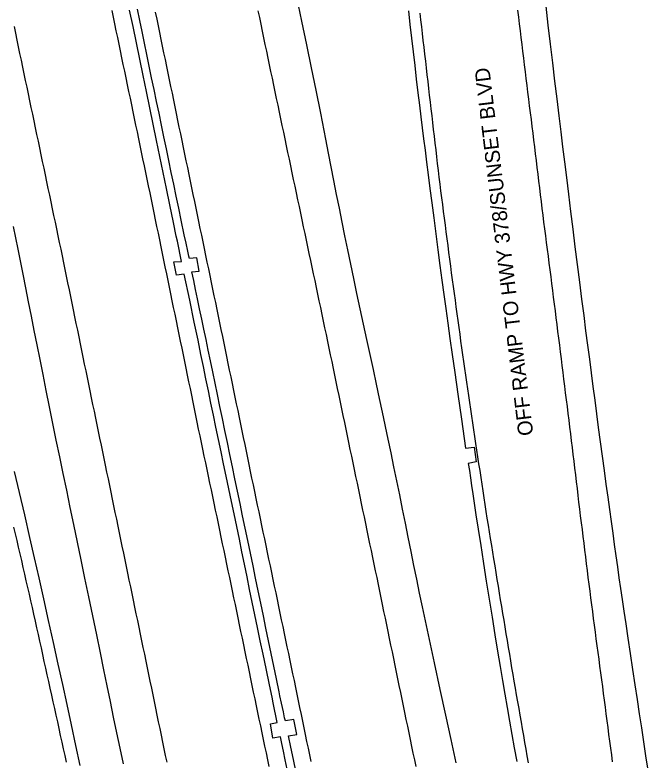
# Model space of a CAD drawing. Extents: x 1948091 to 1975253, y 787267 to 823306.
# Drawn here: x 1966599.2 to 1966828.7, y 789115.5 to 789385.7 of the extents above; entities that cross this region are included whole.
import ezdxf

# ---------------------------------------------------------------- set-up
doc = ezdxf.new("R2010")
doc.units = 0
for name, color, linetype in [('RD_EX_Pavement_Markings', 7, 'Continuous'), ('RD_EX_Road', 7, 'Continuous'), ('RD_TX_RoadID', 7, 'Continuous')]:
    doc.layers.add(name, color=color, linetype=linetype)

msp = doc.modelspace()

# ---------------------------------------------------------------- linework, layer by layer
at = {"layer": 'RD_EX_Pavement_Markings'}
for points in [[(1966634.28, 789387.33), (1966634.79, 789384.88), (1966635.3, 789382.44), (1966635.81, 789379.99), (1966636.32, 789377.54), (1966636.83, 789375.1), (1966637.34, 789372.65), (1966637.85, 789370.2), (1966638.36, 789367.75), (1966638.87, 789365.31), (1966639.38, 789362.86), (1966639.89, 789360.41), (1966640.4, 789357.96), (1966640.91, 789355.52), (1966641.42, 789353.07), (1966641.93, 789350.62), (1966642.44, 789348.17), (1966642.95, 789345.73), (1966643.45, 789343.28), (1966643.96, 789340.83), (1966644.47, 789338.38), (1966644.98, 789335.94), (1966645.49, 789333.49), (1966646, 789331.04), (1966646.51, 789328.59), (1966647.02, 789326.15), (1966647.53, 789323.7), (1966648.04, 789321.25), (1966648.54, 789318.8), (1966649.05, 789316.35), (1966649.55, 789313.91), (1966650.06, 789311.46), (1966650.56, 789309.01), (1966651.06, 789306.56), (1966651.57, 789304.11), (1966652.07, 789301.66), (1966652.57, 789299.21), (1966653.08, 789296.76), (1966653.58, 789294.32), (1966654.09, 789291.87), (1966654.59, 789289.42), (1966655.09, 789286.97), (1966655.6, 789284.52), (1966656.1, 789282.07), (1966656.6, 789279.62), (1966657.11, 789277.17), (1966657.61, 789274.73), (1966658.12, 789272.28), (1966658.62, 789269.83), (1966659.12, 789267.38), (1966659.63, 789264.93), (1966660.13, 789262.48), (1966660.64, 789260.03), (1966661.14, 789257.59), (1966661.64, 789255.14), (1966662.15, 789252.69), (1966662.65, 789250.24), (1966663.15, 789247.79), (1966663.66, 789245.34), (1966664.16, 789242.89), (1966664.67, 789240.44), (1966665.17, 789238), (1966665.67, 789235.55), (1966666.18, 789233.1), (1966666.69, 789230.65), (1966667.21, 789228.21), (1966667.72, 789225.76), (1966668.23, 789223.31), (1966668.74, 789220.86), (1966669.25, 789218.42), (1966669.76, 789215.97), (1966670.27, 789213.52), (1966670.78, 789211.08), (1966671.29, 789208.63), (1966671.81, 789206.18), (1966672.32, 789203.73), (1966672.83, 789201.29), (1966673.34, 789198.84), (1966673.85, 789196.39), (1966674.36, 789193.95), (1966674.87, 789191.5), (1966675.38, 789189.05), (1966675.89, 789186.6), (1966676.4, 789184.16), (1966676.92, 789181.71), (1966677.43, 789179.26), (1966677.94, 789176.82), (1966678.45, 789174.37), (1966678.96, 789171.92), (1966679.47, 789169.47), (1966679.98, 789167.03), (1966680.49, 789164.58), (1966681, 789162.13), (1966681.52, 789159.69), (1966682.03, 789157.24), (1966682.54, 789154.79), (1966683.05, 789152.34), (1966683.56, 789149.9), (1966684.07, 789147.45), (1966684.58, 789145), (1966685.09, 789142.55), (1966685.6, 789140.11), (1966686.11, 789137.66), (1966686.62, 789135.21), (1966687.13, 789132.77), (1966687.65, 789130.32), (1966688.16, 789127.87), (1966688.67, 789125.42), (1966689.18, 789122.98), (1966689.69, 789120.53), (1966690.2, 789118.08), (1966690.71, 789115.64), (1966691.22, 789113.19)], [(1966687.27, 789387.21), (1966687.78, 789384.77), (1966688.29, 789382.32), (1966688.8, 789379.87), (1966689.31, 789377.43), (1966689.82, 789374.98), (1966690.33, 789372.53), (1966690.85, 789370.08), (1966691.36, 789367.64), (1966691.87, 789365.19), (1966692.38, 789362.74), (1966692.89, 789360.3), (1966693.4, 789357.85), (1966693.91, 789355.4), (1966694.43, 789352.95), (1966694.94, 789350.51), (1966695.46, 789348.06), (1966695.97, 789345.62), (1966696.49, 789343.17), (1966697, 789340.72), (1966697.52, 789338.28), (1966698.04, 789335.83), (1966698.55, 789333.39), (1966699.07, 789330.94), (1966699.58, 789328.49), (1966700.1, 789326.05), (1966700.62, 789323.6), (1966701.13, 789321.15), (1966701.65, 789318.71), (1966702.16, 789316.26), (1966702.68, 789313.82), (1966703.2, 789311.37), (1966703.71, 789308.92), (1966704.23, 789306.48), (1966704.74, 789304.03), (1966705.26, 789301.59), (1966705.78, 789299.14), (1966706.29, 789296.69), (1966706.81, 789294.25), (1966707.32, 789291.8), (1966707.84, 789289.35), (1966708.35, 789286.91), (1966708.87, 789284.46), (1966709.39, 789282.02), (1966709.9, 789279.57), (1966710.42, 789277.12), (1966710.93, 789274.68), (1966711.45, 789272.23), (1966711.96, 789269.79), (1966712.47, 789267.34), (1966712.98, 789264.89), (1966713.49, 789262.44), (1966714, 789260), (1966714.51, 789257.55), (1966715.02, 789255.1), (1966715.53, 789252.65), (1966716.04, 789250.21), (1966716.55, 789247.76), (1966717.06, 789245.31), (1966717.57, 789242.86), (1966718.08, 789240.42), (1966718.59, 789237.97), (1966719.1, 789235.52), (1966719.61, 789233.07), (1966720.12, 789230.63), (1966720.63, 789228.18), (1966721.14, 789225.73), (1966721.65, 789223.28), (1966722.16, 789220.84), (1966722.67, 789218.39), (1966723.18, 789215.94), (1966723.69, 789213.49), (1966724.2, 789211.05), (1966724.71, 789208.6), (1966725.22, 789206.15), (1966725.73, 789203.71), (1966726.24, 789201.26), (1966726.75, 789198.81), (1966727.26, 789196.36), (1966727.77, 789193.92), (1966728.28, 789191.47), (1966728.79, 789189.02), (1966729.3, 789186.57), (1966729.81, 789184.13), (1966730.31, 789181.68), (1966730.82, 789179.23), (1966731.33, 789176.78), (1966731.83, 789174.33), (1966732.34, 789171.88), (1966732.84, 789169.44), (1966733.35, 789166.99), (1966733.85, 789164.54), (1966734.36, 789162.09), (1966734.86, 789159.64), (1966735.37, 789157.19), (1966735.88, 789154.75), (1966736.38, 789152.3), (1966736.89, 789149.85), (1966737.39, 789147.4), (1966737.9, 789144.95), (1966738.4, 789142.5), (1966738.91, 789140.06), (1966739.41, 789137.61), (1966739.92, 789135.16), (1966740.43, 789132.71), (1966740.93, 789130.26), (1966741.44, 789127.81), (1966741.94, 789125.37), (1966742.45, 789122.92), (1966742.95, 789120.47), (1966743.46, 789118.02), (1966743.96, 789115.57), (1966744.47, 789113.12)], [(1966815.82, 789114.9), (1966815.49, 789117.37), (1966815.16, 789119.85), (1966814.84, 789122.33), (1966814.51, 789124.8), (1966814.19, 789127.28), (1966813.86, 789129.75), (1966813.53, 789132.23), (1966813.21, 789134.71), (1966812.88, 789137.18), (1966812.55, 789139.66), (1966812.23, 789142.13), (1966811.9, 789144.61), (1966811.57, 789147.09), (1966811.24, 789149.56), (1966810.91, 789152.04), (1966810.58, 789154.51), (1966810.25, 789156.99), (1966809.92, 789159.46), (1966809.59, 789161.94), (1966809.26, 789164.41), (1966808.93, 789166.89), (1966808.6, 789169.36), (1966808.26, 789171.84), (1966807.95, 789174.31), (1966807.64, 789176.79), (1966807.33, 789179.27), (1966807.02, 789181.74), (1966806.71, 789184.22), (1966806.4, 789186.7), (1966806.09, 789189.18), (1966805.78, 789191.65), (1966805.47, 789194.13), (1966805.17, 789196.61), (1966804.86, 789199.09), (1966804.55, 789201.56), (1966804.24, 789204.04), (1966803.94, 789206.52), (1966803.64, 789209), (1966803.34, 789211.48), (1966803.04, 789213.96), (1966802.74, 789216.44), (1966802.44, 789218.92), (1966802.14, 789221.39), (1966801.84, 789223.87), (1966801.54, 789226.35), (1966801.24, 789228.83), (1966800.94, 789231.31), (1966800.65, 789233.79), (1966800.35, 789236.27), (1966800.04, 789238.74), (1966799.73, 789241.22), (1966799.43, 789243.7), (1966799.12, 789246.18), (1966798.81, 789248.65), (1966798.5, 789251.13), (1966798.19, 789253.61), (1966797.88, 789256.09), (1966797.57, 789258.56), (1966797.26, 789261.04), (1966796.96, 789263.52), (1966796.65, 789265.99), (1966796.34, 789268.47), (1966796.03, 789270.95), (1966795.72, 789273.43), (1966795.41, 789275.91), (1966795.09, 789278.38), (1966794.77, 789280.86), (1966794.45, 789283.33), (1966794.13, 789285.81), (1966793.82, 789288.29), (1966793.5, 789290.76), (1966793.18, 789293.24), (1966792.86, 789295.72), (1966792.54, 789298.19), (1966792.22, 789300.67), (1966791.9, 789303.15), (1966791.59, 789305.62), (1966791.27, 789308.1), (1966790.95, 789310.58), (1966790.63, 789313.05), (1966790.33, 789315.53), (1966790.02, 789318.01), (1966789.72, 789320.49), (1966789.41, 789322.97), (1966789.11, 789325.45), (1966788.8, 789327.93), (1966788.5, 789330.4), (1966788.19, 789332.88), (1966787.89, 789335.36), (1966787.58, 789337.84), (1966787.28, 789340.32), (1966786.98, 789342.8), (1966786.67, 789345.28), (1966786.37, 789347.75), (1966786.06, 789350.23), (1966785.76, 789352.71), (1966785.46, 789355.19), (1966785.15, 789357.67), (1966784.85, 789360.15), (1966784.54, 789362.62), (1966784.24, 789365.1), (1966783.94, 789367.58), (1966783.63, 789370.06), (1966783.33, 789372.54), (1966783.02, 789375.01), (1966782.72, 789377.49), (1966782.42, 789379.97), (1966782.11, 789382.45), (1966781.82, 789384.93), (1966781.52, 789387.41)], [(1966650.07, 789386.66), (1966650.58, 789384.21), (1966651.08, 789381.76), (1966651.59, 789379.31), (1966652.09, 789376.86), (1966652.6, 789374.42), (1966653.1, 789371.97), (1966653.61, 789369.52), (1966654.11, 789367.07), (1966654.62, 789364.62), (1966655.12, 789362.17), (1966655.63, 789359.73), (1966656.13, 789357.28), (1966656.64, 789354.83), (1966657.14, 789352.38), (1966657.65, 789349.93), (1966658.15, 789347.48), (1966658.66, 789345.03), (1966659.16, 789342.59), (1966659.67, 789340.14), (1966660.17, 789337.69), (1966660.68, 789335.24), (1966661.19, 789332.79), (1966661.69, 789330.35), (1966662.2, 789327.9), (1966662.71, 789325.45), (1966663.22, 789323), (1966663.72, 789320.55), (1966664.23, 789318.11), (1966664.74, 789315.66), (1966665.24, 789313.21), (1966665.75, 789310.76), (1966666.26, 789308.31), (1966666.77, 789305.87), (1966667.27, 789303.42), (1966667.78, 789300.97), (1966668.29, 789298.52), (1966668.79, 789296.07), (1966669.3, 789293.63), (1966669.81, 789291.18), (1966670.32, 789288.73), (1966670.82, 789286.28), (1966671.33, 789283.83), (1966671.84, 789281.39), (1966672.34, 789278.94), (1966672.85, 789276.49), (1966673.36, 789274.04), (1966673.86, 789271.59), (1966674.37, 789269.15), (1966674.88, 789266.7), (1966675.38, 789264.25), (1966675.89, 789261.8), (1966676.39, 789259.35), (1966676.9, 789256.9), (1966677.41, 789254.46), (1966677.91, 789252.01), (1966678.42, 789249.56), (1966678.93, 789247.11), (1966679.43, 789244.66), (1966679.94, 789242.22), (1966680.44, 789239.77), (1966680.95, 789237.32), (1966681.46, 789234.87), (1966681.96, 789232.42), (1966682.47, 789229.97), (1966682.98, 789227.53), (1966683.48, 789225.08), (1966683.99, 789222.63), (1966684.49, 789220.18), (1966685, 789217.73), (1966685.51, 789215.29), (1966686.02, 789212.84), (1966686.53, 789210.39), (1966687.04, 789207.94), (1966687.55, 789205.5), (1966688.06, 789203.05), (1966688.58, 789200.6), (1966689.09, 789198.16), (1966689.6, 789195.71), (1966690.11, 789193.26), (1966690.62, 789190.82), (1966691.14, 789188.37), (1966691.65, 789185.92), (1966692.16, 789183.47), (1966692.67, 789181.03), (1966693.18, 789178.58), (1966693.7, 789176.13), (1966694.21, 789173.69), (1966694.72, 789171.24), (1966695.23, 789168.79), (1966695.74, 789166.35), (1966696.26, 789163.9), (1966696.77, 789161.45), (1966697.28, 789159.01), (1966697.79, 789156.56), (1966698.3, 789154.11), (1966698.82, 789151.66), (1966699.33, 789149.22), (1966699.84, 789146.77), (1966700.35, 789144.32), (1966700.85, 789141.87), (1966701.36, 789139.43), (1966701.87, 789136.98), (1966702.38, 789134.53), (1966702.89, 789132.08), (1966703.4, 789129.64), (1966703.91, 789127.19), (1966704.42, 789124.74), (1966704.93, 789122.29), (1966705.44, 789119.85), (1966705.95, 789117.4), (1966706.46, 789114.95)], [(1966745.94, 789386.37), (1966746.23, 789383.89), (1966746.52, 789381.41), (1966746.8, 789378.93), (1966747.09, 789376.45), (1966747.38, 789373.97), (1966747.66, 789371.48), (1966747.95, 789369), (1966748.24, 789366.52), (1966748.52, 789364.04), (1966748.81, 789361.56), (1966749.1, 789359.08), (1966749.38, 789356.6), (1966749.67, 789354.12), (1966749.96, 789351.64), (1966750.25, 789349.16), (1966750.54, 789346.68), (1966750.83, 789344.2), (1966751.12, 789341.72), (1966751.41, 789339.24), (1966751.7, 789336.76), (1966751.99, 789334.28), (1966752.28, 789331.8), (1966752.57, 789329.32), (1966752.86, 789326.84), (1966753.17, 789324.36), (1966753.49, 789321.88), (1966753.81, 789319.41), (1966754.13, 789316.93), (1966754.45, 789314.45), (1966754.77, 789311.98), (1966755.09, 789309.5), (1966755.41, 789307.02), (1966755.73, 789304.55), (1966756.05, 789302.07), (1966756.37, 789299.6), (1966756.68, 789297.12), (1966757.01, 789294.64), (1966757.35, 789292.17), (1966757.69, 789289.7), (1966758.03, 789287.22), (1966758.37, 789284.75), (1966758.7, 789282.28), (1966759.04, 789279.8), (1966759.38, 789277.33), (1966759.72, 789274.85), (1966760.06, 789272.38), (1966760.4, 789269.91), (1966760.74, 789267.43), (1966761.08, 789264.96), (1966761.43, 789262.49), (1966761.79, 789260.02), (1966762.15, 789257.54), (1966762.51, 789255.07), (1966762.87, 789252.6), (1966763.23, 789250.13), (1966763.59, 789247.66), (1966763.94, 789245.18), (1966764.3, 789242.71), (1966764.66, 789240.24), (1966765.02, 789237.77), (1966765.38, 789235.3), (1966765.75, 789232.83), (1966766.13, 789230.36), (1966766.51, 789227.89), (1966766.88, 789225.42), (1966767.26, 789222.95), (1966767.64, 789220.48), (1966768.02, 789218.02), (1966768.39, 789215.55), (1966768.77, 789213.08), (1966769.15, 789210.61), (1966769.52, 789208.14), (1966769.9, 789205.67), (1966770.29, 789203.21), (1966770.69, 789200.74), (1966771.09, 789198.28), (1966771.49, 789195.81), (1966771.9, 789193.35), (1966772.3, 789190.88), (1966772.7, 789188.42), (1966773.1, 789185.95), (1966773.51, 789183.49), (1966773.91, 789181.02), (1966774.31, 789178.56), (1966774.72, 789176.09), (1966775.12, 789173.63), (1966775.53, 789171.16), (1966775.94, 789168.7), (1966776.35, 789166.24), (1966776.76, 789163.77), (1966777.17, 789161.31), (1966777.58, 789158.84), (1966777.99, 789156.38), (1966778.4, 789153.92), (1966778.81, 789151.45), (1966779.22, 789148.99), (1966779.63, 789146.52), (1966780.05, 789144.06), (1966780.48, 789141.6), (1966780.92, 789139.14), (1966781.35, 789136.68), (1966781.78, 789134.22), (1966782.21, 789131.76), (1966782.64, 789129.3), (1966783.07, 789126.84), (1966783.5, 789124.38), (1966783.93, 789121.92), (1966784.36, 789119.46), (1966784.79, 789117), (1966785.23, 789114.54)], [(1966598.88, 789381.51), (1966599.38, 789379.06), (1966599.89, 789376.61), (1966600.39, 789374.16), (1966600.9, 789371.72), (1966601.4, 789369.27), (1966601.91, 789366.82), (1966602.43, 789364.37), (1966602.94, 789361.93), (1966603.45, 789359.48), (1966603.97, 789357.04), (1966604.48, 789354.59), (1966605, 789352.14), (1966605.51, 789349.7), (1966606.02, 789347.25), (1966606.54, 789344.8), (1966607.05, 789342.36), (1966607.57, 789339.91), (1966608.08, 789337.46), (1966608.59, 789335.02), (1966609.11, 789332.57), (1966609.62, 789330.12), (1966610.13, 789327.68), (1966610.65, 789325.23), (1966611.16, 789322.78), (1966611.68, 789320.34), (1966612.19, 789317.89), (1966612.7, 789315.44), (1966613.22, 789313), (1966613.73, 789310.55), (1966614.25, 789308.1), (1966614.76, 789305.66), (1966615.27, 789303.21), (1966615.78, 789300.76), (1966616.28, 789298.31), (1966616.78, 789295.86), (1966617.29, 789293.42), (1966617.79, 789290.97), (1966618.3, 789288.52), (1966618.8, 789286.07), (1966619.3, 789283.62), (1966619.81, 789281.17), (1966620.31, 789278.72), (1966620.81, 789276.28), (1966621.32, 789273.83), (1966621.82, 789271.38), (1966622.33, 789268.93), (1966622.83, 789266.48), (1966623.33, 789264.03), (1966623.84, 789261.58), (1966624.34, 789259.13), (1966624.84, 789256.69), (1966625.35, 789254.24), (1966625.85, 789251.79), (1966626.36, 789249.34), (1966626.86, 789246.89), (1966627.36, 789244.44), (1966627.87, 789241.99), (1966628.37, 789239.54), (1966628.88, 789237.1), (1966629.38, 789234.65), (1966629.89, 789232.2), (1966630.4, 789229.75), (1966630.9, 789227.3), (1966631.41, 789224.86), (1966631.92, 789222.41), (1966632.42, 789219.96), (1966632.93, 789217.51), (1966633.44, 789215.06), (1966633.94, 789212.62), (1966634.45, 789210.17), (1966634.96, 789207.72), (1966635.46, 789205.27), (1966635.97, 789202.82), (1966636.48, 789200.38), (1966636.98, 789197.93), (1966637.49, 789195.48), (1966638, 789193.03), (1966638.51, 789190.58), (1966639.01, 789188.14), (1966639.52, 789185.69), (1966640.03, 789183.24), (1966640.53, 789180.79), (1966641.04, 789178.34), (1966641.55, 789175.9), (1966642.05, 789173.45), (1966642.56, 789171), (1966643.07, 789168.55), (1966643.57, 789166.1), (1966644.08, 789163.66), (1966644.59, 789161.21), (1966645.09, 789158.76), (1966645.6, 789156.31), (1966646.1, 789153.86), (1966646.61, 789151.41), (1966647.12, 789148.97), (1966647.62, 789146.52), (1966648.13, 789144.07), (1966648.64, 789141.62), (1966649.14, 789139.17), (1966649.65, 789136.73), (1966650.16, 789134.28), (1966650.66, 789131.83), (1966651.17, 789129.38), (1966651.68, 789126.93), (1966652.18, 789124.48), (1966652.69, 789122.04), (1966653.19, 789119.59), (1966653.7, 789117.14), (1966654.21, 789114.69)], [(1966598.7, 789199.98), (1966599.27, 789197.55), (1966599.84, 789195.12), (1966600.41, 789192.69), (1966600.97, 789190.26), (1966601.53, 789187.83), (1966602.08, 789185.39), (1966602.64, 789182.96), (1966603.2, 789180.53), (1966603.76, 789178.09), (1966604.31, 789175.66), (1966604.86, 789173.23), (1966605.41, 789170.79), (1966605.96, 789168.36), (1966606.51, 789165.92), (1966607.06, 789163.49), (1966607.6, 789161.05), (1966608.13, 789158.61), (1966608.67, 789156.17), (1966609.2, 789153.73), (1966609.73, 789151.29), (1966610.27, 789148.85), (1966610.8, 789146.41), (1966611.34, 789143.98), (1966611.88, 789141.54), (1966612.42, 789139.1), (1966612.96, 789136.66), (1966613.5, 789134.22), (1966614.03, 789131.78), (1966614.57, 789129.35), (1966615.11, 789126.91), (1966615.65, 789124.47), (1966616.19, 789122.03), (1966616.73, 789119.59), (1966617.27, 789117.15), (1966617.8, 789114.72)]]:
    msp.add_lwpolyline(points, dxfattribs=at)
at = {"layer": 'RD_EX_Road'}
for points in [[(1966759.13, 789114.48), (1966757.3, 789122.96), (1966755.39, 789131.74), (1966753.36, 789141.06), (1966751.24, 789150.82), (1966750.14, 789155.85), (1966749.04, 789160.93), (1966747.96, 789165.99), (1966746.9, 789171.03), (1966745.86, 789176.05), (1966744.83, 789181.07), (1966743.8, 789186.12), (1966742.77, 789191.18), (1966741.75, 789196.28), (1966740.73, 789201.39), (1966739.7, 789206.51), (1966738.66, 789211.64), (1966737.6, 789216.79), (1966736.55, 789221.9), (1966735.51, 789226.93), (1966734.48, 789231.88), (1966732.43, 789241.63), (1966731.35, 789246.66), (1966730.24, 789251.82), (1966729.1, 789257.12), (1966727.93, 789262.52), (1966726.74, 789267.99), (1966725.54, 789273.53), (1966724.33, 789279.13), (1966723.13, 789284.69), (1966721.99, 789290.11), (1966720.89, 789295.38), (1966719.84, 789300.51), (1966718.82, 789305.55), (1966717.8, 789310.59), (1966716.79, 789315.62), (1966715.79, 789320.63), (1966714.79, 789325.64), (1966713.81, 789330.64), (1966712.84, 789335.62), (1966711.87, 789340.6), (1966710.04, 789350.04), (1966708.35, 789358.46), (1966706.7, 789366.51), (1966705, 789374.83), (1966703.22, 789383.41), (1966701.38, 789392.25)], [(1966697.85, 789112.22), (1966697.15, 789115.63), (1966696.51, 789118.72), (1966695.93, 789121.49), (1966695.43, 789123.94), (1966692.73, 789123.48), (1966691.77, 789128.59), (1966694.3, 789129.19), (1966692.83, 789136.32), (1966692.42, 789138.32), (1966691.49, 789142.81), (1966690.26, 789148.67), (1966689.16, 789153.89), (1966688.13, 789158.76), (1966687.13, 789163.53), (1966686.16, 789168.22), (1966685.21, 789172.82), (1966684.27, 789177.38), (1966683.34, 789181.94), (1966682.41, 789186.49), (1966681.48, 789191.05), (1966680.54, 789195.6), (1966679.6, 789200.17), (1966678.65, 789204.74), (1966677.69, 789209.31), (1966676.73, 789213.88), (1966675.78, 789218.4), (1966674.83, 789222.89), (1966673.89, 789227.34), (1966672.96, 789231.76), (1966672.03, 789236.18), (1966671.12, 789240.59), (1966670.22, 789244.98), (1966669.33, 789249.38), (1966668.43, 789253.78), (1966667.52, 789258.19), (1966666.61, 789262.6), (1966665.55, 789267.73), (1966664.19, 789274.29), (1966662.53, 789282.28), (1966660.57, 789291.71), (1966657.78, 789291.33), (1966656.85, 789296.14), (1966659.55, 789296.35), (1966658.08, 789303.63), (1966657.69, 789305.5), (1966656.68, 789310.46), (1966655.37, 789316.86), (1966654.14, 789322.81), (1966652.95, 789328.57), (1966651.75, 789334.37), (1966650.53, 789340.21), (1966649.31, 789346.09), (1966648.08, 789351.99), (1966646.86, 789357.9), (1966645.65, 789363.79), (1966644.44, 789369.69), (1966643.23, 789375.59), (1966642.01, 789381.49), (1966640.77, 789387.4)], [(1966701.12, 789111), (1966700.13, 789115.76), (1966699.2, 789120.18), (1966698.33, 789124.28), (1966701.36, 789124.82), (1966700.32, 789130.19), (1966697.23, 789129.7), (1966696.96, 789130.84), (1966696.49, 789132.99), (1966695.82, 789136.15), (1966695.27, 789138.83), (1966694.95, 789140.31), (1966693.99, 789144.97), (1966693.03, 789149.6), (1966692.08, 789154.19), (1966691.13, 789158.75), (1966690.19, 789163.29), (1966689.25, 789167.83), (1966688.32, 789172.36), (1966687.38, 789176.9), (1966686.44, 789181.44), (1966685.5, 789185.98), (1966684.56, 789190.53), (1966683.61, 789195.08), (1966682.67, 789199.62), (1966681.73, 789204.12), (1966680.79, 789208.59), (1966679.86, 789213.03), (1966678.93, 789217.45), (1966678.01, 789221.86), (1966677.1, 789226.27), (1966676.2, 789230.67), (1966675.3, 789235.06), (1966674.4, 789239.41), (1966673.51, 789243.72), (1966672.63, 789248.01), (1966671.75, 789252.22), (1966670.9, 789256.32), (1966670.07, 789260.3), (1966669.26, 789264.17), (1966668.47, 789267.97), (1966667.69, 789271.72), (1966666.91, 789275.44), (1966666.14, 789279.13), (1966665.4, 789282.71), (1966664.69, 789286.14), (1966664.01, 789289.41), (1966663.37, 789292.53), (1966666.02, 789292.83), (1966665.16, 789297.6), (1966662.42, 789297.35), (1966662.23, 789298.18), (1966661.83, 789300.05), (1966661.22, 789302.94), (1966660.58, 789306.02), (1966659.49, 789311.28), (1966658.57, 789315.66), (1966657.67, 789320.01), (1966656.77, 789324.32), (1966655.88, 789328.61), (1966654.99, 789332.91), (1966654.1, 789337.2), (1966653.21, 789341.49), (1966652.32, 789345.78), (1966651.43, 789350.07), (1966650.54, 789354.37), (1966649.64, 789358.66), (1966648.75, 789362.94), (1966647.87, 789367.18), (1966647, 789371.38), (1966646.15, 789375.53), (1966645.31, 789379.65), (1966644.47, 789383.74), (1966643.63, 789387.79)], [(1966741.79, 789387.14), (1966742.36, 789382.23), (1966742.94, 789377.27), (1966743.52, 789372.3), (1966744.1, 789367.33), (1966744.68, 789362.36), (1966745.25, 789357.52), (1966745.8, 789352.98), (1966746.32, 789348.73), (1966746.82, 789344.77), (1966747.32, 789340.84), (1966747.85, 789336.69), (1966748.4, 789332.3), (1966748.99, 789327.69), (1966749.6, 789322.8), (1966750.26, 789317.61), (1966750.97, 789312.12), (1966751.71, 789306.32), (1966752.47, 789300.48), (1966753.21, 789294.88), (1966753.93, 789289.51), (1966754.63, 789284.39), (1966755.34, 789279.27), (1966756.08, 789273.94), (1966756.85, 789268.38), (1966757.66, 789262.61), (1966758.58, 789256.08), (1966759.71, 789248.24), (1966761.03, 789239.1), (1966762.56, 789228.66), (1966765.59, 789229.02), (1966766.35, 789223.6), (1966763.53, 789223.07), (1966763.9, 789220.52), (1966764.3, 789217.84), (1966764.71, 789215.04), (1966765.14, 789212.11), (1966765.65, 789208.69), (1966766.3, 789204.41), (1966767.09, 789199.27), (1966768.01, 789193.28), (1966768.39, 789190.87), (1966769.02, 789186.84), (1966770.04, 789180.36), (1966771.09, 789173.86), (1966772.14, 789167.33), (1966773.18, 789160.98), (1966774.16, 789155.03), (1966775.09, 789149.49), (1966775.95, 789144.35), (1966776.79, 789139.42), (1966777.64, 789134.52), (1966778.48, 789129.65), (1966779.33, 789124.8), (1966780.2, 789119.93), (1966781.08, 789114.99)], [(1966828.68, 789111.9), (1966827.9, 789117.02), (1966827.12, 789122.13), (1966826.36, 789127.22), (1966825.61, 789132.3), (1966824.84, 789137.48), (1966824.05, 789142.84), (1966823.21, 789148.4), (1966822.35, 789154.15), (1966821.5, 789159.76), (1966820.73, 789164.89), (1966820.03, 789169.54), (1966819.41, 789173.72), (1966818.83, 789177.67), (1966818.25, 789181.64), (1966817.68, 789185.62), (1966817.12, 789189.62), (1966816.55, 789193.67), (1966815.97, 789197.81), (1966815.38, 789202.03), (1966814.78, 789206.34), (1966814.16, 789210.82), (1966813.51, 789215.53), (1966812.84, 789220.48), (1966812.13, 789225.67), (1966811.43, 789230.92), (1966810.74, 789236.06), (1966810.08, 789241.1), (1966809.45, 789246.02), (1966808.82, 789250.92), (1966808.18, 789255.87), (1966807.53, 789260.88), (1966806.87, 789265.94), (1966806.18, 789271.19), (1966805.46, 789276.76), (1966804.7, 789282.65), (1966803.9, 789288.86), (1966803.08, 789295.24), (1966802.27, 789301.62), (1966801.48, 789308.02), (1966800.69, 789314.44), (1966799.93, 789320.71), (1966799.19, 789326.71), (1966798.49, 789332.44), (1966797.83, 789337.88), (1966797.16, 789343.34), (1966796.45, 789349.12), (1966795.71, 789355.23), (1966794.94, 789361.66), (1966794.14, 789368.3), (1966793.34, 789375.06), (1966792.52, 789381.94), (1966791.7, 789388.94)], [(1966598.54, 789308.99), (1966600.25, 789300.76), (1966602.05, 789291.72), (1966603.02, 789286.75), (1966604.01, 789281.62), (1966605.03, 789276.47), (1966606.06, 789271.3), (1966607.11, 789266.1), (1966608.18, 789260.79), (1966609.29, 789255.27), (1966610.44, 789249.55), (1966611.62, 789243.63), (1966612.82, 789237.61), (1966614.05, 789231.56), (1966615.29, 789225.51), (1966616.55, 789219.44), (1966617.83, 789213.33), (1966619.11, 789207.14), (1966620.4, 789200.88), (1966621.71, 789194.55), (1966623.03, 789188.09), (1966624.41, 789181.48), (1966625.82, 789174.71), (1966627.28, 789167.78), (1966628.72, 789160.94), (1966630.08, 789154.43), (1966631.35, 789148.26), (1966632.53, 789142.42), (1966633.68, 789136.76), (1966634.85, 789131.09), (1966636.04, 789125.43), (1966637.24, 789119.77), (1966638.44, 789114.16)], [(1966622.89, 789113.48), (1966621.32, 789120.83), (1966619.71, 789128.26), (1966618.1, 789135.66), (1966616.53, 789142.89), (1966614.92, 789150.27), (1966613.18, 789158.12), (1966611.39, 789166.12), (1966609.63, 789173.97), (1966607.93, 789181.57), (1966606.31, 789188.83), (1966604.62, 789196.26), (1966602.74, 789204.4), (1966600.82, 789212.58), (1966599.06, 789220.13)]]:
    msp.add_lwpolyline(points, dxfattribs=at)

# ---------------------------------------------------------------- texts
at = {"layer": 'RD_TX_RoadID'}
msp.add_text('OFF RAMP TO HWY 378/SUNSET BLVD', height=5.4, rotation=96.825, dxfattribs=at).set_placement((1966787.1, 789233.42))

doc.saveas('drawing.dxf')
